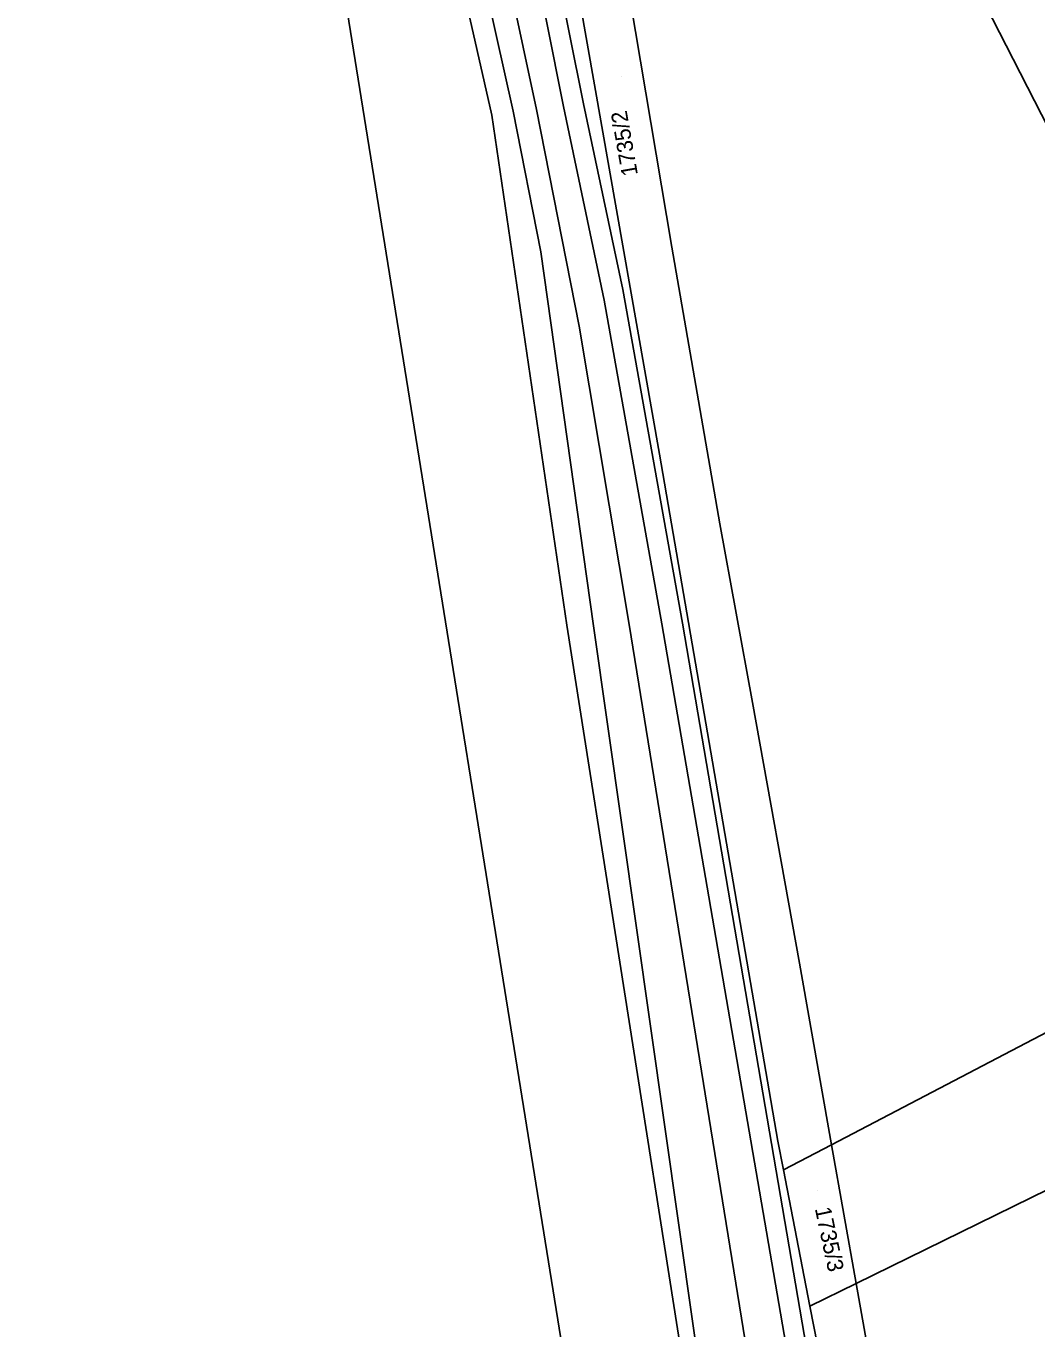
# Model space of a CAD drawing. Extents: x -263943 to -261149, y -1236934 to -1230686.
# Drawn here: x -262965.3 to -262839.6, y -1236013.1 to -1235851.1 of the extents above; entities that cross this region are included whole.
import ezdxf

# ---------------------------------------------------------------- set-up
doc = ezdxf.new("R2010")
doc.units = 0
for name, color, linetype in [('body_kn', 7, 'Continuous'), ('kladpar_druhypozemkov', 7, 'Continuous'), ('kladpar_hranice', 7, 'Continuous'), ('kladpar_parcelnecisla', 7, 'Continuous'), ('kladpar_plochy', 7, 'Continuous'), ('zappar_hrandruhpozemk', 7, 'Continuous'), ('zuob_linie', 7, 'Continuous'), ('zuob_plochy', 7, 'Continuous')]:
    doc.layers.add(name, color=color, linetype=linetype)

msp = doc.modelspace()

# ---------------------------------------------------------------- linework, layer by layer
at = {"layer": 'body_kn'}
for p, q in [((-262843.44, -1235853.52), (-262843.44, -1235853.52)), ((-262896, -1235860.76), (-262896, -1235860.76)), ((-262907.38, -1235862.17), (-262907.38, -1235862.17)), ((-262904.73, -1235861.69), (-262904.73, -1235861.69)), ((-262901.85, -1235861.49), (-262901.85, -1235861.49)), ((-262898.47, -1235861.09), (-262898.47, -1235861.09)), ((-262885, -1235878.61), (-262885, -1235878.61)), ((-262901.29, -1235879.16), (-262901.29, -1235879.16)), ((-262891.12, -1235883.85), (-262891.12, -1235883.85)), ((-262893.41, -1235885.2), (-262893.41, -1235885.2)), ((-262896.55, -1235888.42), (-262896.55, -1235888.42)), ((-262886.55, -1235904.35), (-262886.55, -1235904.35)), ((-262879.02, -1235912.99), (-262879.02, -1235912.99)), ((-262898.05, -1235925.58), (-262898.05, -1235925.58)), ((-262890.32, -1235925.52), (-262890.32, -1235925.52)), ((-262886.25, -1235925.44), (-262886.25, -1235925.44)), ((-262883.7, -1235925.36), (-262883.7, -1235925.36)), ((-262894.74, -1235925.68), (-262894.74, -1235925.68)), ((-262874.97, -1235935.23), (-262874.97, -1235935.23)), ((-262869.14, -1235967.65), (-262869.14, -1235967.65)), ((-262871.84, -1235989.76), (-262871.84, -1235989.76)), ((-262865.14, -1235990.21), (-262865.14, -1235990.21)), ((-262865.14, -1235990.21), (-262865.14, -1235990.21)), ((-262871.14, -1235993.35), (-262871.14, -1235993.35)), ((-262871.14, -1235993.35), (-262871.14, -1235993.35)), ((-262862.08, -1236007.46), (-262862.08, -1236007.46)), ((-262867.84, -1236010.28), (-262867.84, -1236010.28))]:
    msp.add_line(p, q, dxfattribs=at)
at = {"layer": 'kladpar_druhypozemkov'}
for p, q in [((-262891.23, -1235857.37), (-262891.23, -1235857.37)), ((-262866.93, -1235995.93), (-262866.93, -1235995.93))]:
    msp.add_line(p, q, dxfattribs=at)
at = {"layer": 'kladpar_hranice'}
for points in [[(-262862.53, -1236240.1), (-262895.12, -1236037.24), (-262925.77, -1235846.85), (-262929.73, -1235828.25), (-262939.45, -1235789.51), (-262946.58, -1235769.15), (-262958.73, -1235737.77), (-262962.25, -1235729.74), (-262985.32, -1235684.29), (-263049.8, -1235562.15), (-263053.02, -1235556.09), (-263100.02, -1235467.82), (-263130.9, -1235410.32), (-263287.4, -1235108.1)], [(-262707.73, -1236150.88), (-262717.99, -1236121.07), (-262742.82, -1236057.73), (-262755.44, -1236025.13), (-262784.83, -1235967.96), (-262812.71, -1235913.51), (-262843.44, -1235853.52), (-262866.2, -1235809.08), (-262895.53, -1235751.97), (-262912.34, -1235720.17), (-262918.74, -1235723.18), (-262929.39, -1235728.18), (-262941.55, -1235698.09), (-262962.24, -1235644.69), (-262994.36, -1235576.33)], [(-262994.36, -1235576.33), (-262962.24, -1235644.69), (-262941.55, -1235698.09), (-262929.39, -1235728.18), (-262914.19, -1235765.79), (-262902.73, -1235812.42), (-262886.55, -1235904.35), (-262871.84, -1235989.76), (-262871.14, -1235993.35), (-262867.84, -1236010.28), (-262863.55, -1236032.23), (-262856.6, -1236071.12), (-262850.82, -1236103.24), (-262844.94, -1236135.73)], [(-262829.23, -1236194.7), (-262844.53, -1236106.63), (-262850.7, -1236071.61), (-262859.1, -1236024.25), (-262862.08, -1236007.46), (-262786.1, -1235970.21), (-262791.6, -1235961.47), (-262796.19, -1235954.16), (-262865.14, -1235990.21), (-262869.14, -1235967.65), (-262874.97, -1235935.23), (-262879.02, -1235912.99), (-262885, -1235878.61), (-262892.14, -1235836.25), (-262901.12, -1235783.44), (-262918.74, -1235723.18), (-262912.34, -1235720.17), (-262895.53, -1235751.97), (-262866.2, -1235809.08), (-262843.44, -1235853.52), (-262812.71, -1235913.51), (-262784.83, -1235967.96), (-262755.44, -1236025.13), (-262742.82, -1236057.73)], [(-262865.14, -1235990.21), (-262871.14, -1235993.35), (-262871.84, -1235989.76), (-262886.55, -1235904.35), (-262902.73, -1235812.42), (-262914.19, -1235765.79), (-262929.39, -1235728.18), (-262918.74, -1235723.18), (-262901.12, -1235783.44), (-262892.14, -1235836.25), (-262885, -1235878.61), (-262879.02, -1235912.99), (-262874.97, -1235935.23), (-262869.14, -1235967.65), (-262865.14, -1235990.21)], [(-262865.14, -1235990.21), (-262796.19, -1235954.16), (-262791.6, -1235961.47), (-262786.1, -1235970.21), (-262862.08, -1236007.46), (-262865.14, -1235990.21)], [(-262871.14, -1235993.35), (-262865.14, -1235990.21), (-262862.08, -1236007.46), (-262867.84, -1236010.28), (-262871.14, -1235993.35)], [(-262844.94, -1236135.73), (-262850.82, -1236103.24), (-262856.6, -1236071.12), (-262863.55, -1236032.23), (-262867.84, -1236010.28), (-262862.08, -1236007.46), (-262859.1, -1236024.25), (-262850.7, -1236071.61), (-262844.53, -1236106.63)]]:
    msp.add_lwpolyline(points, dxfattribs=at)
at = {"layer": 'kladpar_plochy'}
for points in [[(-262707.73, -1236150.88), (-262717.99, -1236121.07), (-262742.82, -1236057.73), (-262755.44, -1236025.13), (-262784.83, -1235967.96), (-262812.71, -1235913.51), (-262843.44, -1235853.52), (-262866.2, -1235809.08), (-262895.53, -1235751.97), (-262912.34, -1235720.17), (-262918.74, -1235723.18), (-262929.39, -1235728.18), (-262941.55, -1235698.09), (-262962.24, -1235644.69), (-262994.36, -1235576.33)], [(-262994.36, -1235576.33), (-262962.24, -1235644.69), (-262941.55, -1235698.09), (-262929.39, -1235728.18), (-262914.19, -1235765.79), (-262902.73, -1235812.42), (-262886.55, -1235904.35), (-262871.84, -1235989.76), (-262871.14, -1235993.35), (-262867.84, -1236010.28), (-262863.55, -1236032.23), (-262856.6, -1236071.12), (-262850.82, -1236103.24), (-262844.94, -1236135.73)], [(-262862.53, -1236240.1), (-262895.12, -1236037.24), (-262925.77, -1235846.85), (-262929.73, -1235828.25), (-262939.45, -1235789.51), (-262946.58, -1235769.15), (-262958.73, -1235737.77), (-262962.25, -1235729.74), (-262985.32, -1235684.29)], [(-262866.2, -1235809.08), (-262843.44, -1235853.52), (-262812.71, -1235913.51), (-262784.83, -1235967.96), (-262755.44, -1236025.13), (-262742.82, -1236057.73), (-262717.99, -1236121.07), (-262707.73, -1236150.88)], [(-262829.23, -1236194.7), (-262844.53, -1236106.63), (-262850.7, -1236071.61), (-262859.1, -1236024.25), (-262862.08, -1236007.46), (-262786.1, -1235970.21), (-262791.6, -1235961.47), (-262796.19, -1235954.16), (-262865.14, -1235990.21), (-262869.14, -1235967.65), (-262874.97, -1235935.23), (-262879.02, -1235912.99), (-262885, -1235878.61), (-262892.14, -1235836.25)], [(-262844.94, -1236135.73), (-262850.82, -1236103.24), (-262856.6, -1236071.12), (-262863.55, -1236032.23), (-262867.84, -1236010.28), (-262862.08, -1236007.46), (-262859.1, -1236024.25), (-262850.7, -1236071.61), (-262844.53, -1236106.63), (-262829.23, -1236194.7)]]:
    msp.add_lwpolyline(points, dxfattribs=at)
for points in [[(-262865.14, -1235990.21), (-262871.14, -1235993.35), (-262871.84, -1235989.76), (-262886.55, -1235904.35), (-262902.73, -1235812.42), (-262914.19, -1235765.79), (-262929.39, -1235728.18), (-262918.74, -1235723.18), (-262901.12, -1235783.44), (-262892.14, -1235836.25), (-262885, -1235878.61), (-262879.02, -1235912.99), (-262874.97, -1235935.23), (-262869.14, -1235967.65)], [(-262865.14, -1235990.21), (-262796.19, -1235954.16), (-262791.6, -1235961.47), (-262786.1, -1235970.21), (-262862.08, -1236007.46)], [(-262871.14, -1235993.35), (-262865.14, -1235990.21), (-262862.08, -1236007.46), (-262867.84, -1236010.28)]]:
    msp.add_lwpolyline(points, close=True, dxfattribs=at)
at = {"layer": 'zappar_hrandruhpozemk'}
for p, q in [((-262901.29, -1235879.16), (-262894.74, -1235925.68)), ((-262891.12, -1235883.85), (-262883.7, -1235925.36)), ((-262893.41, -1235885.2), (-262886.25, -1235925.44)), ((-262896.55, -1235888.42), (-262890.32, -1235925.52)), ((-262898.05, -1235925.58), (-262882.45, -1236024.89))]:
    msp.add_line(p, q, dxfattribs=at)
for points in [[(-262917.65, -1235763.13), (-262914.64, -1235773.65), (-262906.61, -1235807.92), (-262896, -1235860.76), (-262891.12, -1235883.85)], [(-262920.09, -1235764.35), (-262916.99, -1235774.49), (-262909.02, -1235808.2), (-262898.47, -1235861.09), (-262893.41, -1235885.2)], [(-262924.45, -1235766.84), (-262913.06, -1235808.92), (-262901.85, -1235861.49), (-262896.55, -1235888.42)], [(-262928.96, -1235767.11), (-262916.46, -1235809.08), (-262904.73, -1235861.69), (-262901.29, -1235879.16)], [(-262932.03, -1235768.48), (-262919.06, -1235810.79), (-262907.38, -1235862.17), (-262898.05, -1235925.58)], [(-262890.32, -1235925.52), (-262874.25, -1236024.84), (-262853.97, -1236150.36)], [(-262886.25, -1235925.44), (-262869.09, -1236025.12), (-262847.83, -1236149.57), (-262840.51, -1236193.1)], [(-262883.7, -1235925.36), (-262866.63, -1236024.97), (-262845.16, -1236148.59), (-262836.95, -1236193.85)], [(-262894.74, -1235925.68), (-262880.59, -1236025.23), (-262860.06, -1236150.5)]]:
    msp.add_lwpolyline(points, dxfattribs=at)
at = {"layer": 'zuob_linie'}
msp.add_lwpolyline([(-262862.53, -1236240.1), (-262895.12, -1236037.24), (-262925.77, -1235846.85), (-262929.73, -1235828.25), (-262939.45, -1235789.51), (-262946.58, -1235769.15), (-262958.73, -1235737.77), (-262962.25, -1235729.74), (-262985.32, -1235684.29), (-263049.8, -1235562.15), (-263053.02, -1235556.09), (-263100.02, -1235467.82), (-263130.9, -1235410.32), (-263287.4, -1235108.1)], dxfattribs=at)
at = {"layer": 'zuob_plochy'}
msp.add_lwpolyline([(-262862.53, -1236240.1), (-262895.12, -1236037.24), (-262925.77, -1235846.85), (-262929.73, -1235828.25), (-262939.45, -1235789.51), (-262946.58, -1235769.15), (-262958.73, -1235737.77), (-262962.25, -1235729.74), (-262985.32, -1235684.29), (-263049.8, -1235562.15), (-263053.02, -1235556.09), (-263100.02, -1235467.82), (-263130.9, -1235410.32), (-263287.4, -1235108.1), (-263274.7, -1235099), (-263272.8, -1235097.5), (-263387.04, -1234882.34), (-263415.79, -1234834.88)], dxfattribs=at)

# ---------------------------------------------------------------- texts
at = {"layer": 'kladpar_parcelnecisla'}
for s, rotation, p in [('1735/2', 100, (-262889.22, -1235869.57)), ('1735/3', 282, (-262867.23, -1235998.15))]:
    msp.add_text(s, height=2, rotation=rotation, dxfattribs=at).set_placement(p)

doc.saveas('drawing.dxf')
